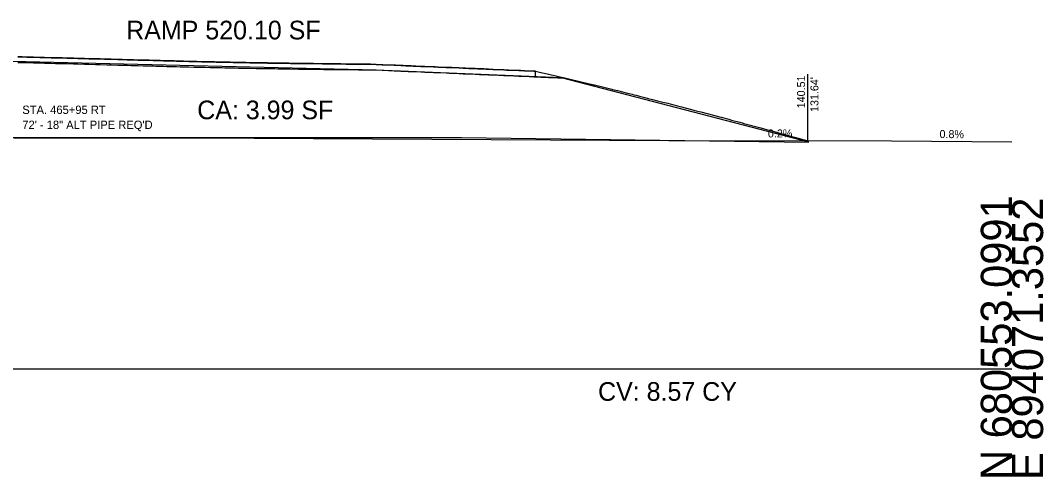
# Model space of a CAD drawing. Extents: x -26 to 4303, y -13 to 10775.
# Drawn here: x 1210.8 to 1302.8, y 4490.3 to 4531.3 of the extents above; entities that cross this region are included whole.
import ezdxf

# ---------------------------------------------------------------- set-up
doc = ezdxf.new("R2010")
doc.units = 0
for name, color, linetype in [('CONST_LV3', 7, 'Continuous'), ('DTM_P_FINISHED_GRADE', 7, 'Continuous'), ('DTM_X_GROUND', 7, 'Continuous'), ('X_PROFILES_1', 7, 'Continuous'), ('XS_CELL', 7, 'Continuous'), ('XS_M_SHAPES_EARTHWORK', 7, 'Continuous'), ('XS_P_DR_GRAVEL', 7, 'Continuous'), ('XS_P_DRAINAGE', 7, 'Continuous'), ('XS_P_GROUND', 7, 'Continuous'), ('XS_P_TX_CLEARZONE', 7, 'Continuous'), ('XS_P_TX_FS_BS', 7, 'Continuous'), ('XS_SHEET_EW_TX_AREA', 7, 'Continuous'), ('XS_SHEET_EW_TX_VOLUME', 7, 'Continuous')]:
    doc.layers.add(name, color=color, linetype=linetype)

msp = doc.modelspace()

# ---------------------------------------------------------------- linework, layer by layer
at = {"layer": 'CONST_LV3'}
msp.add_lwpolyline([(1210.596, 4528.067), (1211, 4528.057), (1211.404, 4528.046), (1212, 4528.03), (1212.596, 4528.014), (1213, 4528.004), (1213.596, 4527.988), (1214, 4527.977), (1214.404, 4527.966), (1215, 4527.95), (1215.597, 4527.935), (1216, 4527.924), (1216.597, 4527.908), (1217, 4527.897), (1217.403, 4527.887), (1218, 4527.871), (1218.403, 4527.86), (1219, 4527.844), (1219.597, 4527.828), (1220, 4527.818), (1220.449, 4527.805), (1220.755, 4527.797), (1220.76, 4527.797), (1220.863, 4527.794), (1220.959, 4527.791), (1221, 4527.789), (1221.403, 4527.779), (1221.882, 4527.765), (1222, 4527.761), (1222.406, 4527.751), (1222.787, 4527.74), (1222.999, 4527.733), (1223.41, 4527.723), (1223.694, 4527.715), (1223.997, 4527.707), (1224.416, 4527.697), (1224.65, 4527.691), (1224.994, 4527.681), (1225.423, 4527.671), (1225.516, 4527.668), (1225.735, 4527.663), (1226.208, 4527.652), (1226.431, 4527.647), (1226.708, 4527.639), (1227.165, 4527.629), (1227.352, 4527.624), (1227.438, 4527.621), (1227.913, 4527.612), (1228.278, 4527.603), (1228.446, 4527.599), (1228.941, 4527.59), (1229.211, 4527.583), (1229.452, 4527.578), (1229.971, 4527.568), (1230.15, 4527.564), (1230.419, 4527.559), (1230.726, 4527.553), (1231.002, 4527.548), (1231.096, 4527.546), (1231.459, 4527.539), (1232.033, 4527.529), (1232.052, 4527.528), (1232.25, 4527.524), (1232.858, 4527.515), (1233.049, 4527.511), (1233.065, 4527.509), (1233.712, 4527.5), (1233.992, 4527.495), (1234.096, 4527.493), (1234.782, 4527.483), (1234.979, 4527.48), (1235.338, 4527.475), (1235.483, 4527.473), (1235.854, 4527.468), (1235.978, 4527.466), (1236.156, 4527.463), (1236.927, 4527.454), (1236.991, 4527.453), (1237.184, 4527.45), (1238, 4527.441), (1238.036, 4527.44), (1238.107, 4527.439), (1238.989, 4527.43), (1239.061, 4527.429), (1239.075, 4527.428), (1240.031, 4527.42), (1240.121, 4527.419), (1240.148, 4527.418), (1240.642, 4527.414), (1240.7, 4527.414), (1241.204, 4527.41), (1241.221, 4527.409), (1242.167, 4527.402), (1242.294, 4527.397), (1242.297, 4527.397), (1242.298, 4527.397), (1242.301, 4527.397), (1243.364, 4527.353), (1243.416, 4527.351), (1243.438, 4527.35), (1244.433, 4527.309), (1244.558, 4527.304), (1244.576, 4527.303), (1245.5, 4527.264), (1245.715, 4527.255), (1245.724, 4527.255), (1246.164, 4527.236), (1246.423, 4527.226), (1246.853, 4527.207), (1246.915, 4527.205), (1247.013, 4527.201), (1247.186, 4527.194), (1247.991, 4527.159), (1248.135, 4527.154), (1248.413, 4527.143), (1249.128, 4527.111), (1249.384, 4527.101), (1249.641, 4527.091), (1250.264, 4527.063), (1250.665, 4527.047), (1250.872, 4527.039), (1251.398, 4527.015), (1251.981, 4526.991), (1252.103, 4526.987), (1252.326, 4526.977), (1252.719, 4526.96), (1252.915, 4526.951), (1253.333, 4526.933), (1254.298, 4526.891), (1254.566, 4526.879), (1254.725, 4526.874), (1255.655, 4526.833), (1255.797, 4526.827), (1256.159, 4526.812), (1257.015, 4526.775), (1257.028, 4526.775), (1257.154, 4526.769)], dxfattribs=at)
at = {"layer": 'DTM_P_FINISHED_GRADE'}
msp.add_lwpolyline([(1210.597, 4528.067), (1211, 4528.057), (1211.002, 4528.057), (1211.597, 4528.041), (1212, 4528.03), (1212.002, 4528.03), (1212.598, 4528.014), (1213, 4528.004), (1213.002, 4528.003), (1213.598, 4527.988), (1214, 4527.977), (1214.002, 4527.977), (1214.598, 4527.961), (1215, 4527.95), (1215.002, 4527.95), (1215.598, 4527.934), (1216, 4527.924), (1216.002, 4527.924), (1216.598, 4527.908), (1217, 4527.897), (1217.002, 4527.897), (1217.599, 4527.881), (1218, 4527.871), (1218.002, 4527.871), (1218.599, 4527.855), (1219, 4527.844), (1219.002, 4527.844), (1219.599, 4527.828), (1220, 4527.818), (1220.002, 4527.818), (1220.45, 4527.805), (1220.755, 4527.797), (1220.76, 4527.797), (1220.863, 4527.794), (1220.959, 4527.791), (1220.961, 4527.791), (1221.002, 4527.789), (1221.403, 4527.779), (1221.882, 4527.765), (1221.883, 4527.765), (1222.001, 4527.761), (1222.406, 4527.751), (1222.787, 4527.74), (1222.789, 4527.74), (1223.001, 4527.733), (1223.41, 4527.723), (1223.694, 4527.715), (1223.696, 4527.715), (1223.999, 4527.707), (1224.416, 4527.697), (1224.65, 4527.691), (1224.651, 4527.691), (1224.864, 4527.687), (1225.209, 4527.676), (1225.423, 4527.671), (1225.516, 4527.668), (1225.517, 4527.668), (1225.99, 4527.657), (1226.431, 4527.647), (1226.433, 4527.647), (1226.71, 4527.639), (1227.165, 4527.629), (1227.352, 4527.624), (1227.354, 4527.624), (1227.44, 4527.621), (1227.913, 4527.612), (1228.278, 4527.603), (1228.28, 4527.603), (1228.447, 4527.599), (1228.941, 4527.59), (1229.211, 4527.583), (1229.212, 4527.583), (1229.469, 4527.578), (1229.71, 4527.573), (1229.971, 4527.568), (1230.15, 4527.564), (1230.152, 4527.564), (1230.458, 4527.558), (1231.002, 4527.548), (1231.096, 4527.546), (1231.099, 4527.545), (1231.461, 4527.539), (1232.033, 4527.529), (1232.052, 4527.528), (1232.054, 4527.528), (1232.252, 4527.524), (1232.858, 4527.515), (1233.05, 4527.511), (1233.052, 4527.511), (1233.067, 4527.509), (1233.712, 4527.5), (1233.992, 4527.495), (1233.995, 4527.495), (1234.099, 4527.493), (1234.435, 4527.488), (1234.636, 4527.485), (1234.979, 4527.48), (1234.982, 4527.48), (1235.129, 4527.477), (1235.854, 4527.468), (1235.978, 4527.466), (1235.981, 4527.466), (1236.159, 4527.463), (1236.927, 4527.454), (1236.991, 4527.453), (1236.994, 4527.452), (1237.187, 4527.45), (1238.001, 4527.441), (1238.036, 4527.44), (1238.039, 4527.44), (1238.111, 4527.439), (1238.989, 4527.43), (1239.061, 4527.429), (1239.065, 4527.429), (1239.078, 4527.428), (1239.544, 4527.424), (1239.651, 4527.423), (1240.121, 4527.419), (1240.125, 4527.419), (1240.152, 4527.418), (1241.165, 4527.41), (1241.204, 4527.41), (1241.208, 4527.41), (1241.225, 4527.409), (1242.167, 4527.402), (1242.294, 4527.397), (1242.297, 4527.397), (1242.298, 4527.397), (1242.302, 4527.397), (1242.305, 4527.397), (1243.364, 4527.353), (1243.417, 4527.351), (1243.42, 4527.351), (1243.442, 4527.35), (1244.433, 4527.309), (1244.558, 4527.304), (1244.562, 4527.303), (1244.58, 4527.303), (1245.057, 4527.283), (1245.248, 4527.275), (1245.715, 4527.255), (1245.724, 4527.255), (1245.727, 4527.255), (1245.965, 4527.245), (1246.853, 4527.207), (1246.915, 4527.205), (1246.919, 4527.205), (1247.017, 4527.201), (1247.189, 4527.194), (1247.991, 4527.159), (1248.135, 4527.154), (1248.138, 4527.154), (1248.416, 4527.142), (1249.128, 4527.111), (1249.384, 4527.101), (1249.387, 4527.101), (1249.644, 4527.091), (1250.264, 4527.063), (1250.665, 4527.047), (1250.668, 4527.047), (1250.874, 4527.039), (1251.148, 4527.027), (1251.738, 4527.002), (1251.981, 4526.991), (1251.983, 4526.991), (1252.105, 4526.987), (1252.505, 4526.97), (1252.915, 4526.951), (1253.333, 4526.933), (1253.335, 4526.933), (1254.299, 4526.891), (1254.566, 4526.879), (1254.725, 4526.874), (1254.726, 4526.874), (1255.655, 4526.833), (1255.797, 4526.827), (1256.159, 4526.812), (1256.159, 4526.812), (1257.015, 4526.775), (1257.028, 4526.775), (1257.154, 4526.769)], dxfattribs=at)
at = {"layer": 'DTM_X_GROUND'}
msp.add_lwpolyline([(1000, 4527.047), (1012.653, 4521.36), (1015.589, 4520.9), (1030.406, 4519.586), (1040.857, 4518.334), (1059.518, 4517.394), (1100.052, 4515.401), (1117.74, 4513.76), (1122.892, 4513.417), (1126.763, 4513.627), (1141.699, 4515.779), (1144.696, 4517.139), (1149.906, 4516.828), (1149.956, 4516.833), (1176.709, 4519.611), (1183.124, 4519.79), (1194.202, 4520.766), (1195.632, 4520.835), (1210.279, 4520.767), (1231.863, 4520.749), (1269.14, 4520.527), (1289.173, 4520.495), (1300, 4520.407)], dxfattribs=at)
at = {"layer": 'XS_CELL'}
msp.add_line((1150, 4500), (1300, 4500), dxfattribs=at)
at = {"layer": 'XS_P_DR_GRAVEL'}
for points in [[(1210.597, 4527.567), (1211, 4527.557), (1211.002, 4527.557), (1211.597, 4527.541), (1212, 4527.53), (1212.002, 4527.53), (1212.598, 4527.514), (1213, 4527.504), (1213.002, 4527.503), (1213.598, 4527.488), (1214, 4527.477), (1214.002, 4527.477), (1214.598, 4527.461), (1215, 4527.45), (1215.002, 4527.45), (1215.598, 4527.434), (1216, 4527.424), (1216.002, 4527.424), (1216.598, 4527.408), (1217, 4527.397), (1217.002, 4527.397), (1217.599, 4527.381), (1218, 4527.371), (1218.002, 4527.371), (1218.599, 4527.355), (1219, 4527.344), (1219.002, 4527.344), (1219.599, 4527.328), (1220, 4527.318), (1220.002, 4527.318), (1220.45, 4527.305), (1220.755, 4527.297), (1220.76, 4527.297), (1220.863, 4527.294), (1220.959, 4527.291), (1220.961, 4527.291), (1221.002, 4527.289), (1221.403, 4527.279), (1221.882, 4527.265), (1221.883, 4527.265), (1222.001, 4527.261), (1222.406, 4527.251), (1222.787, 4527.24), (1222.789, 4527.24), (1223.001, 4527.233), (1223.41, 4527.223), (1223.694, 4527.215), (1223.696, 4527.215), (1223.999, 4527.207), (1224.416, 4527.197), (1224.65, 4527.191), (1224.651, 4527.191), (1224.864, 4527.187), (1225.209, 4527.176), (1225.423, 4527.171), (1225.516, 4527.168), (1225.517, 4527.168), (1225.99, 4527.157), (1226.431, 4527.147), (1226.433, 4527.147), (1226.71, 4527.139), (1227.165, 4527.129), (1227.352, 4527.124), (1227.354, 4527.124), (1227.44, 4527.121), (1227.913, 4527.112), (1228.278, 4527.103), (1228.28, 4527.103), (1228.447, 4527.099), (1228.941, 4527.09), (1229.211, 4527.083), (1229.212, 4527.083), (1229.469, 4527.078), (1229.71, 4527.073), (1229.971, 4527.068), (1230.15, 4527.064), (1230.152, 4527.064), (1230.458, 4527.058), (1231.002, 4527.048), (1231.096, 4527.046), (1231.099, 4527.045), (1231.461, 4527.039), (1232.033, 4527.029), (1232.052, 4527.028), (1232.054, 4527.028), (1232.252, 4527.024), (1232.858, 4527.015), (1233.05, 4527.011), (1233.052, 4527.011), (1233.067, 4527.009), (1233.712, 4527), (1233.992, 4526.995), (1233.995, 4526.995), (1234.099, 4526.993), (1234.435, 4526.988), (1234.636, 4526.985), (1234.979, 4526.98), (1234.982, 4526.98), (1235.129, 4526.977), (1235.854, 4526.968), (1235.978, 4526.966), (1235.981, 4526.966), (1236.159, 4526.963), (1236.927, 4526.954), (1236.991, 4526.953), (1236.994, 4526.952), (1237.187, 4526.95), (1238.001, 4526.941), (1238.036, 4526.94), (1238.039, 4526.94), (1238.111, 4526.939), (1238.989, 4526.93), (1239.061, 4526.929), (1239.065, 4526.929), (1239.078, 4526.928), (1239.544, 4526.924), (1239.651, 4526.923), (1240.121, 4526.919), (1240.125, 4526.919), (1240.152, 4526.918), (1241.165, 4526.91), (1241.204, 4526.91), (1241.208, 4526.91), (1241.225, 4526.909), (1242.167, 4526.902), (1242.294, 4526.897), (1242.297, 4526.897), (1242.298, 4526.897), (1242.302, 4526.897), (1242.305, 4526.897), (1243.364, 4526.853), (1243.417, 4526.851), (1243.42, 4526.851), (1243.442, 4526.85), (1244.433, 4526.809), (1244.558, 4526.804), (1244.562, 4526.803), (1244.58, 4526.803), (1245.057, 4526.783), (1245.248, 4526.775), (1245.715, 4526.755), (1245.724, 4526.755), (1245.727, 4526.755), (1245.965, 4526.745), (1246.853, 4526.707), (1246.915, 4526.705), (1246.919, 4526.705), (1247.017, 4526.701), (1247.189, 4526.694), (1247.991, 4526.659), (1248.135, 4526.654), (1248.138, 4526.654), (1248.416, 4526.642), (1249.128, 4526.611), (1249.384, 4526.601), (1249.387, 4526.601), (1249.644, 4526.591), (1250.264, 4526.563), (1250.665, 4526.547), (1250.668, 4526.547), (1250.874, 4526.539), (1251.148, 4526.527), (1251.738, 4526.502), (1251.981, 4526.491), (1251.983, 4526.491), (1252.105, 4526.487), (1252.505, 4526.47), (1252.915, 4526.451), (1253.333, 4526.433), (1253.335, 4526.433), (1254.299, 4526.391), (1254.566, 4526.379), (1254.725, 4526.374), (1254.726, 4526.374), (1255.655, 4526.333), (1255.797, 4526.327), (1256.159, 4526.312), (1256.159, 4526.312), (1257.015, 4526.275), (1257.028, 4526.275), (1257.154, 4526.269), (1257.154, 4526.769), (1257.028, 4526.775), (1257.015, 4526.775), (1256.159, 4526.812), (1256.159, 4526.812), (1255.797, 4526.827), (1255.655, 4526.833), (1254.726, 4526.874), (1254.725, 4526.874), (1254.566, 4526.879), (1254.299, 4526.891), (1253.335, 4526.933), (1253.333, 4526.933), (1252.915, 4526.951), (1252.505, 4526.97), (1252.105, 4526.987), (1251.983, 4526.991), (1251.981, 4526.991), (1251.738, 4527.002), (1251.148, 4527.027), (1250.874, 4527.039), (1250.668, 4527.047), (1250.665, 4527.047), (1250.264, 4527.063), (1249.644, 4527.091), (1249.387, 4527.101), (1249.384, 4527.101), (1249.128, 4527.111), (1248.416, 4527.142), (1248.138, 4527.154), (1248.135, 4527.154), (1247.991, 4527.159), (1247.189, 4527.194), (1247.017, 4527.201), (1246.919, 4527.205), (1246.915, 4527.205), (1246.853, 4527.207), (1245.965, 4527.245), (1245.727, 4527.255), (1245.724, 4527.255), (1245.715, 4527.255), (1245.248, 4527.275), (1245.057, 4527.283), (1244.58, 4527.303), (1244.562, 4527.303), (1244.558, 4527.304), (1244.433, 4527.309), (1243.442, 4527.35), (1243.42, 4527.351), (1243.417, 4527.351), (1243.364, 4527.353), (1242.305, 4527.397), (1242.302, 4527.397), (1242.298, 4527.397), (1242.297, 4527.397), (1242.294, 4527.397), (1242.167, 4527.402), (1241.225, 4527.409), (1241.208, 4527.41), (1241.204, 4527.41), (1241.165, 4527.41), (1240.152, 4527.418), (1240.125, 4527.419), (1240.121, 4527.419), (1239.651, 4527.423), (1239.544, 4527.424), (1239.078, 4527.428), (1239.065, 4527.429), (1239.061, 4527.429), (1238.989, 4527.43), (1238.111, 4527.439), (1238.039, 4527.44), (1238.036, 4527.44), (1238.001, 4527.441), (1237.187, 4527.45), (1236.994, 4527.452), (1236.991, 4527.453), (1236.927, 4527.454), (1236.159, 4527.463), (1235.981, 4527.466), (1235.978, 4527.466), (1235.854, 4527.468), (1235.129, 4527.477), (1234.982, 4527.48), (1234.979, 4527.48), (1234.636, 4527.485), (1234.435, 4527.488), (1234.099, 4527.493), (1233.995, 4527.495), (1233.992, 4527.495), (1233.712, 4527.5), (1233.067, 4527.509), (1233.052, 4527.511), (1233.05, 4527.511), (1232.858, 4527.515), (1232.252, 4527.524), (1232.054, 4527.528), (1232.052, 4527.528), (1232.033, 4527.529), (1231.461, 4527.539), (1231.099, 4527.545), (1231.096, 4527.546), (1231.002, 4527.548), (1230.458, 4527.558), (1230.152, 4527.564), (1230.15, 4527.564), (1229.971, 4527.568), (1229.71, 4527.573), (1229.469, 4527.578), (1229.212, 4527.583), (1229.211, 4527.583), (1228.941, 4527.59), (1228.447, 4527.599), (1228.28, 4527.603), (1228.278, 4527.603), (1227.913, 4527.612), (1227.44, 4527.621), (1227.354, 4527.624), (1227.352, 4527.624), (1227.165, 4527.629), (1226.71, 4527.639), (1226.433, 4527.647), (1226.431, 4527.647), (1225.99, 4527.657), (1225.517, 4527.668), (1225.516, 4527.668), (1225.423, 4527.671), (1225.209, 4527.676), (1224.864, 4527.687), (1224.651, 4527.691), (1224.65, 4527.691), (1224.416, 4527.697), (1223.999, 4527.707), (1223.696, 4527.715), (1223.694, 4527.715), (1223.41, 4527.723), (1223.001, 4527.733), (1222.789, 4527.74), (1222.787, 4527.74), (1222.406, 4527.751), (1222.001, 4527.761), (1221.883, 4527.765), (1221.882, 4527.765), (1221.403, 4527.779), (1221.002, 4527.789), (1220.961, 4527.791), (1220.959, 4527.791), (1220.863, 4527.794), (1220.76, 4527.797), (1220.755, 4527.797), (1220.45, 4527.805), (1220.002, 4527.818), (1220, 4527.818), (1219.599, 4527.828), (1219.002, 4527.844), (1219, 4527.844), (1218.599, 4527.855), (1218.002, 4527.871), (1218, 4527.871), (1217.599, 4527.881), (1217.002, 4527.897), (1217, 4527.897), (1216.598, 4527.908), (1216.002, 4527.924), (1216, 4527.924), (1215.598, 4527.934), (1215.002, 4527.95), (1215, 4527.95), (1214.598, 4527.961), (1214.002, 4527.977), (1214, 4527.977), (1213.598, 4527.988), (1213.002, 4528.003), (1213, 4528.004), (1212.598, 4528.014), (1212.002, 4528.03), (1212, 4528.03), (1211.597, 4528.041), (1211.002, 4528.057), (1211, 4528.057), (1210.597, 4528.067)], [(1257.154, 4526.269), (1257.639, 4526.249), (1258.32, 4526.22), (1258.982, 4526.191), (1259.167, 4526.183), (1259.654, 4526.163), (1259.818, 4526.156)]]:
    msp.add_lwpolyline(points, dxfattribs=at)
at = {"layer": 'XS_P_GROUND'}
msp.add_lwpolyline([(1257.154, 4526.769), (1257.639, 4526.66), (1257.654, 4526.656), (1258.32, 4526.504), (1258.355, 4526.496), (1258.982, 4526.351), (1258.997, 4526.347), (1259.167, 4526.308), (1259.212, 4526.298), (1259.654, 4526.195), (1259.781, 4526.165), (1260.749, 4525.936), (1260.794, 4525.926), (1261.029, 4525.871), (1261.275, 4525.813), (1262.387, 4525.544), (1262.432, 4525.534), (1262.446, 4525.531), (1262.809, 4525.443), (1263.91, 4525.172), (1264.033, 4525.143), (1264.086, 4525.13), (1264.516, 4525.025), (1265.422, 4524.799), (1265.581, 4524.76), (1265.852, 4524.693), (1265.985, 4524.66), (1266.197, 4524.606), (1266.519, 4524.526), (1266.986, 4524.407), (1267.297, 4524.33), (1267.69, 4524.23), (1268.125, 4524.12), (1268.607, 4523.996), (1269.05, 4523.882), (1269.47, 4523.772), (1269.919, 4523.658), (1270.287, 4523.564), (1271.072, 4523.36), (1271.605, 4523.22), (1271.874, 4523.15), (1272.033, 4523.109), (1273.162, 4522.811), (1273.697, 4522.668), (1273.741, 4522.657), (1273.848, 4522.629), (1274.534, 4522.446), (1274.782, 4522.378), (1275.52, 4522.18), (1275.737, 4522.12), (1275.77, 4522.112), (1275.888, 4522.081), (1277.424, 4521.665), (1277.708, 4521.587), (1278.128, 4521.474), (1278.19, 4521.457), (1279.651, 4521.056), (1279.765, 4521.025), (1280.41, 4520.846), (1280.44, 4520.837), (1281.637, 4520.507)], dxfattribs=at)
at = {"layer": 'XS_P_TX_CLEARZONE'}
msp.add_line((1281.637, 4520.507), (1281.637, 4526.507), dxfattribs=at)
msp.add_line((1281.637, 4520.507), (1281.637, 4526.507), dxfattribs=at)
msp.add_line((1281.637, 4520.507), (1281.637, 4526.507), dxfattribs=at)
at = {"layer": 'XS_SHEET_EW_TX_AREA'}
msp.add_lwpolyline([(1175.807, 4528.507), (1180, 4527.447), (1199.895, 4520.821), (1250.502, 4520.821), (1281.73, 4520.394), (1259.496, 4526.178), (1242.835, 4526.875), (1182.296, 4528.319)], close=True, dxfattribs=at)

# ---------------------------------------------------------------- texts
at = {"layer": 'X_PROFILES_1'}
msp.add_text('X', height=0.12, dxfattribs=at).set_placement((1281.598, 4520.447))
at = {"layer": 'XS_CELL'}
for s, p in [('N 680553.0991', (1300, 4490)), ('E 894071.3552', (1302.8, 4490))]:
    msp.add_text(s, height=2.8, rotation=90, dxfattribs=at).set_placement(p)
at = {"layer": 'XS_M_SHAPES_EARTHWORK'}
msp.add_text('CV: 8.57 CY', height=1.68, dxfattribs=at).set_placement((1262.78, 4497.12))
at = {"layer": 'XS_P_DRAINAGE'}
for s, p in [('STA. 465+95 RT', (1211.006, 4522.926)), ('72\' - 18" ALT PIPE REQ\'D', (1211.006, 4521.576))]:
    msp.add_text(s, height=0.75, dxfattribs=at).set_placement(p)
at = {"layer": 'XS_P_TX_CLEARZONE'}
for s, p in [('140.51', (1281.397, 4523.436)), ('140.51', (1281.397, 4523.436)), ('140.51', (1281.397, 4523.436)), ("131.64'", (1282.597, 4523.107)), ("131.64'", (1282.597, 4523.107)), ("131.64'", (1282.597, 4523.107))]:
    msp.add_text(s, height=0.72, rotation=90, dxfattribs=at).set_placement(p)
at = {"layer": 'XS_P_TX_FS_BS'}
for s, rotation, p in [('0.2%', 359.90873, (1278.055, 4520.813)), ('0.8%', 359.53485, (1293.487, 4520.76))]:
    msp.add_text(s, height=0.72, rotation=rotation, dxfattribs=at).set_placement(p)
at = {"layer": 'XS_SHEET_EW_TX_VOLUME'}
for s, p in [('RAMP 520.10 SF', (1220.35, 4529.632)), ('CA: 3.99 SF', (1226.736, 4522.449))]:
    msp.add_text(s, height=1.68, dxfattribs=at).set_placement(p)

doc.saveas('drawing.dxf')
